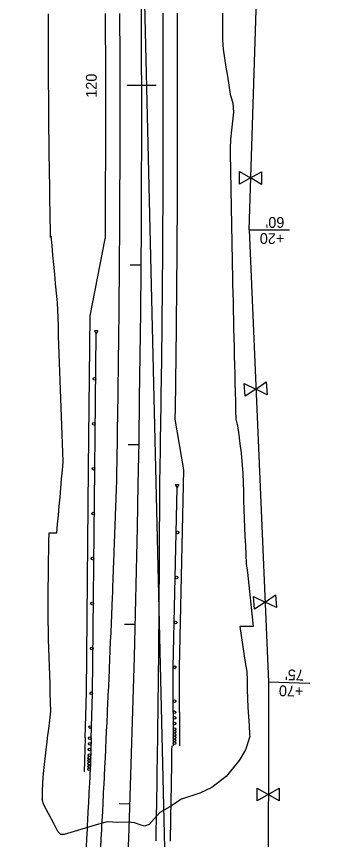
# Model space of a CAD drawing. Extents: x 634057 to 641016, y 287858 to 292331.
# Drawn here: x 634256.5 to 634429.5, y 290444.8 to 290902.9 of the extents above; entities that cross this region are included whole.
import ezdxf

# ---------------------------------------------------------------- set-up
doc = ezdxf.new("R2010")
doc.units = 0
for name, color, linetype in [('53', 7, 'Continuous'), ('R_50 Horz Alg PC PI PT', 7, 'Continuous'), ('R_50 Horz Alg Stations', 7, 'Continuous'), ('R_50 Horz Alg Ticks', 7, 'Continuous'), ('R_Draft', 7, 'Continuous'), ('R_Horz Alg', 7, 'Continuous'), ('R_No Plot', 7, 'Continuous'), ('R_Proposed Const Limits', 7, 'Continuous'), ('R_Proposed Road', 7, 'Continuous'), ('R_Proposed Shoulder', 7, 'Continuous'), ('R_ROW', 7, 'Continuous')]:
    doc.layers.add(name, color=color, linetype=linetype)

msp = doc.modelspace()

# ---------------------------------------------------------------- linework, layer by layer
at = {"layer": '53'}
for p, q in [((634385.92, 290784.2), (634408.37, 290784.07)), ((634396.7, 290532.52), (634419.69, 290531.88))]:
    msp.add_line(p, q, dxfattribs=at)
at = {"layer": 'R_50 Horz Alg PC PI PT'}
msp.add_lwpolyline([(634341.05, 290353.77), (634322.94, 291121.85)], dxfattribs=at)
at = {"layer": 'R_50 Horz Alg Ticks'}
for points in [[(634318.12, 290864.54), (634334.12, 290864.56)], [(634319.79, 290764.6), (634325.79, 290764.55)], [(634318.59, 290664.66), (634324.59, 290664.56)], [(634316.52, 290564.73), (634322.52, 290564.58)], [(634313.58, 290464.83), (634319.58, 290464.63)]]:
    msp.add_lwpolyline(points, dxfattribs=at)
at = {"layer": 'R_Draft'}
for p, q in [((634297.39, 290736.2), (634305.89, 290779.16)), ((634296.56, 290651.4), (634297.39, 290736.2)), ((634299.81, 290727.91), (634300.79, 290726.17)), ((634301.81, 290727.89), (634299.81, 290727.91)), ((634300.05, 290651.16), (634300.79, 290726.17)), ((634301.81, 290727.89), (634300.79, 290726.17)), ((634349.51, 290650.61), (634344.82, 290678.72)), ((634295.33, 290526.38), (634296.56, 290651.4)), ((634298.83, 290526.14), (634300.05, 290651.16)), ((634347.22, 290540.55), (634349.51, 290650.61)), ((634343.72, 290540.62), (634345.8, 290640.61)), ((634344.83, 290642.36), (634345.8, 290640.61)), ((634344.83, 290642.36), (634346.83, 290642.32)), ((634346.83, 290642.32), (634345.8, 290640.61)), ((634343.7, 290515.62), (634343.72, 290540.62)), ((634347.2, 290515.62), (634347.22, 290540.62)), ((634294.59, 290501.46), (634295.34, 290526.45)), ((634298.08, 290501.15), (634298.83, 290526.14)), ((634343.7, 290515.62), (634343.68, 290496.87)), ((634347.2, 290515.62), (634347.18, 290496.87)), ((634294.59, 290501.46), (634294.03, 290482.51)), ((634298.08, 290501.15), (634297.52, 290482.41))]:
    msp.add_line(p, q, dxfattribs=at)
for centre in [(634299.79, 290701.17), (634299.55, 290676.18), (634299.3, 290651.18), (634299.06, 290626.18), (634346.03, 290615.63), (634298.81, 290601.18), (634345.51, 290590.63), (634298.57, 290576.18), (634344.99, 290565.64), (634298.32, 290551.18), (634344.47, 290540.64), (634298.08, 290526.18), (634344.45, 290521.87), (634344.45, 290515.62), (634344.44, 290512.5), (634344.44, 290509.37), (634297.52, 290507.42), (634344.44, 290506.25), (634297.33, 290501.17), (634344.43, 290501.56), (634344.44, 290504.69), (634344.44, 290503.12), (634297.24, 290498.05), (634344.43, 290500), (634344.43, 290498.44), (634297.05, 290491.8), (634297.14, 290494.93), (634296.91, 290487.12), (634296.96, 290488.68), (634297, 290490.24), (634296.82, 290483.99), (634296.87, 290485.56)]:
    msp.add_circle(centre, 0.75, dxfattribs=at)
at = {"layer": 'R_Horz Alg'}
msp.add_arc((622866.97, 290851.82), 11459.16, 353.678846, 1.350269, dxfattribs=at)
at = {"layer": 'R_Proposed Const Limits'}
for points in [[(634270.89, 290467.15), (634271.01, 290471.25), (634271.06, 290476.55), (634271.5, 290481.52), (634272.08, 290486.48), (634272.65, 290491.45), (634273.23, 290496.41), (634273.54, 290499.06), (634273.81, 290501.38), (634274.38, 290506.35), (634274.96, 290511.31), (634275.5, 290516.28), (634275.4, 290521.28), (634275.29, 290526.28), (634275.19, 290531.28), (634275.02, 290536.28), (634274.84, 290541.28), (634274.67, 290546.29), (634274.51, 290551.29), (634274.34, 290556.29), (634274.19, 290561.3), (634274.05, 290566.29), (634274.05, 290566.3), (634274.02, 290570.59), (634274.05, 290575.58), (634274.1, 290580.57), (634274.16, 290585.55), (634274.22, 290590.54), (634274.29, 290595.53), (634274.36, 290600.52), (634274.45, 290605.5), (634274.54, 290610.49), (634274.62, 290615.47), (634278.85, 290615.41), (634279.34, 290620.39), (634279.81, 290625.37), (634280.26, 290630.35), (634280.72, 290635.34), (634281.16, 290640.32), (634281.58, 290645.3), (634282.02, 290650.28), (634282.4, 290655.26), (634282.4, 290655.27), (634282.22, 290660.25), (634282.02, 290665.24), (634281.83, 290670.24), (634281.64, 290675.23), (634281.45, 290680.22), (634281.26, 290685.21), (634281.06, 290690.2), (634280.87, 290695.19), (634280.69, 290700.18), (634280.5, 290705.17), (634280.32, 290710.16), (634280.14, 290715.15), (634280, 290720.15), (634279.87, 290725.14), (634279.75, 290730.13), (634279.63, 290735.12), (634279.19, 290743.67), (634278.7, 290748.95), (634278.2, 290754.24), (634277.71, 290759.53), (634277.23, 290764.82), (634276.74, 290770.11), (634276.26, 290775.39), (634275.8, 290780.68), (634275.44, 290779.87), (634275.33, 290784.85), (634275.26, 290789.83), (634275.17, 290794.81), (634275.09, 290799.78), (634275.01, 290804.76), (634274.94, 290809.74), (634274.87, 290814.72), (634274.8, 290819.7), (634274.73, 290824.67), (634274.66, 290829.65), (634274.6, 290834.63), (634274.55, 290839.61), (634274.5, 290844.59), (634274.45, 290849.56), (634274.41, 290854.54), (634274.37, 290859.52), (634274.35, 290864.49), (634274.33, 290869.47), (634274.32, 290874.45), (634274.3, 290879.43), (634274.29, 290884.4), (634274.28, 290889.38), (634274.26, 290894.36), (634274.25, 290899.34), (634274.24, 290904.31)], [(634371.03, 290904.76), (634371.05, 290899.74), (634371.06, 290894.72), (634371.08, 290889.7), (634371.37, 290884.68), (634372.17, 290879.66), (634372.97, 290874.65), (634373.77, 290869.63), (634374.58, 290864.61), (634375.39, 290859.59), (634376.84, 290854.56), (634377.2, 290849.54), (634376.66, 290844.52), (634376.13, 290839.5), (634375.6, 290834.48), (634375.31, 290829.46), (634375.38, 290824.44), (634375.46, 290819.41), (634375.55, 290814.39), (634375.65, 290809.37), (634375.73, 290804.35), (634375.82, 290799.33), (634375.92, 290794.3), (634376.03, 290789.28), (634376.14, 290784.26), (634376.25, 290779.24), (634376.26, 290778.82), (634376.35, 290774.21), (634376.44, 290769.19), (634376.53, 290764.17), (634376.63, 290759.14), (634376.73, 290754.12), (634376.83, 290749.1), (634376.94, 290744.07), (634377.05, 290739.05), (634377.16, 290734.03), (634377.28, 290729), (634377.42, 290723.98), (634377.56, 290718.95), (634377.64, 290713.93), (634377.73, 290708.9), (634377.88, 290703.88), (634378, 290698.85), (634378.1, 290693.83), (634378.23, 290688.8), (634378.39, 290683.78), (634378.49, 290678.75), (634379.46, 290675.13), (634380.12, 290670.06), (634380.77, 290664.99), (634381.46, 290659.93), (634381.46, 290659.92), (634382.37, 290648.58), (634382.51, 290643.57), (634382.67, 290638.55), (634382.85, 290633.54), (634383.01, 290628.53), (634383.19, 290623.51), (634383.4, 290618.5), (634383.57, 290613.48), (634383.57, 290613.47), (634383.78, 290608.46), (634384, 290603.45), (634384.21, 290598.43), (634384.91, 290593.41), (634388.17, 290563.28), (634380.63, 290563.4), (634381.4, 290558.38), (634382.17, 290553.36), (634382.93, 290548.33), (634383.73, 290543.31), (634384.54, 290538.28), (634384.81, 290533.27), (634384.89, 290528.25), (634384.98, 290523.24), (634385.15, 290518.22), (634385.56, 290513.2), (634385.86, 290508.19), (634386.15, 290503.17), (634386.21, 290502.19)], [(634386.21, 290502.19), (634383.91, 290494.64), (634380.34, 290488.84), (634373.15, 290479.83), (634365.05, 290473.84), (634358.46, 290470.57), (634348.24, 290467.19), (634341.77, 290463.07), (634336.27, 290459.82), (634333.07, 290456.38), (634330.35, 290453.23), (634327.75, 290452.26), (634325.33, 290452.99), (634322.19, 290454.02), (634318.68, 290454.5), (634312.88, 290454.26), (634306.89, 290454.62), (634302.06, 290453.41)], [(634302.06, 290453.41), (634282.99, 290447.53), (634281.16, 290447.63), (634279.41, 290449.26), (634277.29, 290453.68), (634271.65, 290464.14), (634270.82, 290467.15)]]:
    msp.add_lwpolyline(points, dxfattribs=at)
at = {"layer": 'R_Proposed Road'}
for points in [[(634303.38, 290440.19), (634303.65, 290445.18), (634303.91, 290450.17), (634304.03, 290452.58), (634304.16, 290455.15), (634304.42, 290460.14), (634304.67, 290465.13), (634304.92, 290470.12), (634305.12, 290474.14), (634305.17, 290475.11), (634305.42, 290480.09), (634305.66, 290485.08), (634305.9, 290490.07), (634306.14, 290495.06), (634306.18, 290495.7), (634306.38, 290500.05), (634306.62, 290505.04), (634306.85, 290510.03), (634307.08, 290515.02), (634307.19, 290517.26), (634307.31, 290520), (634307.54, 290524.99), (634307.76, 290529.98), (634307.99, 290534.97), (634308.16, 290538.83), (634308.21, 290539.96), (634308.43, 290544.95), (634308.64, 290549.94), (634308.86, 290554.93), (634309.07, 290559.92), (634309.09, 290560.39), (634309.28, 290564.91), (634309.48, 290569.91), (634309.69, 290574.9), (634309.89, 290579.89), (634309.98, 290581.96), (634310.09, 290584.88), (634310.29, 290589.87), (634310.49, 290594.86), (634310.68, 290599.85), (634310.82, 290603.54), (634310.87, 290604.84), (634311.06, 290609.83), (634311.25, 290614.83), (634311.44, 290619.82), (634311.62, 290624.81), (634311.63, 290625.11), (634311.8, 290629.8), (634311.98, 290634.79), (634312.16, 290639.79), (634312.25, 290644.78), (634312.28, 290646.69), (634312.34, 290649.77), (634312.43, 290654.77), (634312.51, 290659.76), (634312.59, 290664.76), (634312.65, 290668.27), (634312.67, 290669.75), (634312.75, 290674.75), (634312.83, 290679.74), (634312.9, 290684.73), (634312.98, 290689.73), (634312.98, 290689.86), (634313.04, 290694.72), (634313.11, 290699.72), (634313.18, 290704.71), (634313.24, 290709.7), (634313.26, 290711.44), (634313.3, 290714.7), (634313.36, 290719.69), (634313.42, 290724.69), (634313.47, 290729.68), (634313.51, 290733.03), (634313.52, 290734.68), (634313.57, 290739.67), (634313.62, 290744.67), (634313.67, 290749.66), (634313.71, 290754.61), (634313.71, 290754.66), (634313.75, 290759.65), (634313.79, 290764.64), (634313.83, 290769.64), (634313.86, 290774.63), (634313.87, 290776.2), (634313.9, 290779.63), (634313.93, 290784.62), (634313.95, 290789.62), (634313.98, 290794.61), (634314, 290797.79), (634314, 290799.61), (634314.03, 290804.6), (634314.05, 290809.6), (634314.06, 290814.59), (634314.08, 290819.37), (634314.08, 290819.59), (634314.09, 290824.58), (634314.1, 290829.58), (634314.11, 290834.57), (634314.12, 290839.57), (634314.12, 290840.96), (634314.12, 290844.56), (634314.12, 290849.55), (634314.12, 290854.55), (634314.12, 290859.54), (634314.12, 290862.55), (634314.12, 290864.54), (634314.11, 290869.53), (634314.1, 290874.53), (634314.09, 290879.52), (634314.08, 290884.13), (634314.08, 290884.52), (634314.06, 290889.51), (634314.04, 290894.51), (634314.02, 290899.5), (634314, 290904.5)], [(634334.13, 290444.1), (634334.22, 290449.1), (634334.26, 290451.53), (634334.31, 290454.11), (634334.4, 290459.12), (634334.49, 290464.12), (634334.57, 290469.13), (634334.64, 290473.17), (634334.66, 290474.13), (634334.74, 290479.14), (634334.81, 290484.15), (634334.89, 290489.15), (634334.96, 290494.16), (634334.97, 290494.8), (634335.04, 290499.17), (634335.1, 290504.17), (634335.17, 290509.18), (634335.24, 290514.19), (634335.27, 290516.44), (634335.3, 290519.19), (634335.36, 290524.2), (634335.42, 290529.21), (634335.48, 290534.21), (634335.52, 290538.08), (634335.53, 290539.22), (634335.58, 290544.22), (634335.63, 290549.23), (634335.68, 290554.24), (634335.72, 290559.24), (634335.73, 290559.72), (634335.77, 290564.25), (634335.81, 290569.26), (634335.85, 290574.26), (634335.88, 290579.27), (634335.9, 290581.35), (634335.92, 290584.28), (634335.95, 290589.28), (634335.98, 290594.29), (634336.01, 290599.29), (634336.03, 290602.99), (634336.04, 290604.3), (634336.06, 290609.31), (634336.08, 290614.31), (634336.1, 290619.32), (634336.12, 290624.32), (634336.12, 290624.62), (634336.13, 290629.33), (634336.14, 290634.34), (634336.15, 290639.34), (634336.25, 290644.35), (634336.28, 290646.26), (634336.34, 290649.35), (634336.42, 290654.36), (634336.51, 290659.36), (634336.59, 290664.36), (634336.65, 290667.89), (634336.67, 290669.37), (634336.75, 290674.37), (634336.83, 290679.38), (634336.9, 290684.38), (634336.97, 290689.39), (634336.97, 290689.52), (634337.04, 290694.39), (634337.11, 290699.4), (634337.18, 290704.4), (634337.24, 290709.41), (634337.26, 290711.15), (634337.3, 290714.41), (634337.36, 290719.42), (634337.42, 290724.42), (634337.47, 290729.43), (634337.51, 290732.78), (634337.52, 290734.43), (634337.57, 290739.44), (634337.62, 290744.44), (634337.67, 290749.45), (634337.71, 290754.41), (634337.71, 290754.45), (634337.75, 290759.46), (634337.79, 290764.46), (634337.83, 290769.47), (634337.86, 290774.47), (634337.87, 290776.04), (634337.89, 290779.48), (634337.93, 290784.48), (634337.95, 290789.49), (634337.98, 290794.49), (634338, 290797.67), (634338, 290799.5), (634338.03, 290804.5), (634338.04, 290809.51), (634338.06, 290814.51), (634338.08, 290819.3), (634338.08, 290819.52), (634338.09, 290824.52), (634338.1, 290829.53), (634338.11, 290834.53), (634338.12, 290839.54), (634338.12, 290840.94), (634338.12, 290844.54), (634338.12, 290849.55), (634338.12, 290854.56), (634338.12, 290859.56), (634338.12, 290862.57), (634338.12, 290864.57), (634338.11, 290869.57), (634338.1, 290874.58), (634338.09, 290879.58), (634338.08, 290884.2), (634338.08, 290884.59), (634338.06, 290889.59), (634338.04, 290894.6), (634338.02, 290899.6), (634338, 290904.61)]]:
    msp.add_lwpolyline(points, dxfattribs=at)
at = {"layer": 'R_Proposed Shoulder'}
for points in [[(634305.89, 290779.16), (634305.9, 290779.68), (634305.93, 290784.67), (634305.95, 290789.66), (634305.98, 290794.65), (634306, 290797.82), (634306, 290799.64), (634306.03, 290804.63), (634306.05, 290809.63), (634306.06, 290814.62), (634306.08, 290819.4), (634306.08, 290819.61), (634306.09, 290824.6), (634306.1, 290829.59), (634306.11, 290834.58), (634306.12, 290839.57), (634306.12, 290840.97), (634306.12, 290844.57), (634306.12, 290849.56), (634306.12, 290854.55), (634306.12, 290859.54), (634306.12, 290862.54), (634306.12, 290864.53), (634306.11, 290869.52), (634306.1, 290874.51), (634306.09, 290879.5), (634306.08, 290884.11), (634306.08, 290884.5), (634306.06, 290889.49), (634306.04, 290894.48), (634306.02, 290899.47), (634306, 290904.46)], [(634344.82, 290678.72), (634344.83, 290679.26), (634344.9, 290684.27), (634344.97, 290689.27), (634344.97, 290689.4), (634345.04, 290694.28), (634345.11, 290699.29), (634345.17, 290704.3), (634345.24, 290709.31), (634345.26, 290711.05), (634345.3, 290714.32), (634345.36, 290719.32), (634345.41, 290724.33), (634345.47, 290729.34), (634345.5, 290732.69), (634345.52, 290734.35), (634345.57, 290739.36), (634345.62, 290744.37), (634345.67, 290749.38), (634345.71, 290754.34), (634345.71, 290754.38), (634345.75, 290759.39), (634345.79, 290764.4), (634345.83, 290769.41), (634345.86, 290774.42), (634345.87, 290775.99), (634345.89, 290779.43), (634345.93, 290784.44), (634345.95, 290789.44), (634345.98, 290794.45), (634346, 290797.63), (634346, 290799.46), (634346.03, 290804.47), (634346.04, 290809.48), (634346.06, 290814.49), (634346.08, 290819.28), (634346.08, 290819.5), (634346.09, 290824.5), (634346.1, 290829.51), (634346.11, 290834.52), (634346.12, 290839.53), (634346.12, 290840.93), (634346.12, 290844.54), (634346.12, 290849.55), (634346.12, 290854.56), (634346.12, 290859.57), (634346.12, 290862.58), (634346.12, 290864.57), (634346.11, 290869.58), (634346.1, 290874.59), (634346.09, 290879.6), (634346.08, 290884.22), (634346.08, 290884.61), (634346.06, 290889.62), (634346.04, 290894.63), (634346.02, 290899.64), (634346, 290904.64)], [(634342.12, 290443.81), (634342.22, 290448.82), (634342.26, 290451.25), (634342.31, 290453.83), (634342.4, 290458.84), (634342.48, 290463.85), (634342.57, 290468.86), (634342.63, 290472.9), (634342.65, 290473.87), (634342.73, 290478.88), (634342.81, 290483.89), (634342.89, 290488.9), (634342.96, 290493.91), (634342.97, 290494.55), (634343, 290496.88)], [(634295.39, 290440.48), (634295.65, 290445.46), (634295.91, 290450.45), (634296.04, 290452.86), (634296.17, 290455.43), (634296.42, 290460.42), (634296.68, 290465.4), (634296.93, 290470.38), (634297.13, 290474.4), (634297.18, 290475.37), (634297.42, 290480.35), (634297.52, 290482.41)]]:
    msp.add_lwpolyline(points, dxfattribs=at)
at = {"layer": 'R_ROW'}
for p, q in [((634380.51, 290809.5), (634380.57, 290816.57)), ((634386.67, 290812.98), (634380.51, 290809.5)), ((634380.57, 290816.57), (634386.67, 290812.98)), ((634386.67, 290812.98), (634392.82, 290816.47)), ((634392.76, 290809.4), (634386.67, 290812.98)), ((634392.82, 290816.47), (634392.76, 290809.4)), ((634383.22, 290698.56), (634389.58, 290695.47)), ((634383.73, 290691.5), (634383.22, 290698.56)), ((634389.58, 290695.47), (634395.43, 290699.44)), ((634395.43, 290699.44), (634395.94, 290692.38)), ((634389.58, 290695.47), (634383.73, 290691.5)), ((634395.94, 290692.38), (634389.58, 290695.47)), ((634388.4, 290580.07), (634394.76, 290576.98)), ((634388.9, 290573.01), (634388.4, 290580.07)), ((634394.76, 290576.98), (634400.61, 290580.94)), ((634400.61, 290580.94), (634401.12, 290573.89)), ((634394.76, 290576.98), (634388.9, 290573.01)), ((634401.12, 290573.89), (634394.76, 290576.98)), ((634390.42, 290466.32), (634390.43, 290473.4)), ((634396.55, 290469.85), (634390.42, 290466.32)), ((634390.43, 290473.4), (634396.55, 290469.85)), ((634396.55, 290469.85), (634402.67, 290473.39)), ((634402.67, 290466.31), (634396.55, 290469.85)), ((634402.67, 290473.39), (634402.67, 290466.31))]:
    msp.add_line(p, q, dxfattribs=at)
for points in [[(634385.92, 290784.2), (634404.17, 291355.03)], [(634385.92, 290784.2), (634396.7, 290532.52), (634396.26, 290266.17), (634429.51, 290195.43)]]:
    msp.add_lwpolyline(points, dxfattribs=at)

# ---------------------------------------------------------------- texts
at = {"layer": '53'}
for s, rotation, p in [("60'  ", 179.6637, (634405.5, 290791.21)), ('+20 ', 179.6637, (634405.45, 290782.21)), ("75'  ", 178.4137, (634416.4, 290539.26)), ('+70 ', 178.4137, (634416.15, 290530.26))]:
    msp.add_text(s, height=6, rotation=rotation, dxfattribs=at).set_placement(p)
at = {"layer": 'R_50 Horz Alg Stations'}
msp.add_text('120', height=6, rotation=90.0637, dxfattribs=at).set_placement((634301.12, 290857.65))
at = {"layer": 'R_No Plot'}
msp.add_text('+', height=0.1, rotation=87.1576, dxfattribs=at).set_placement((634312.47, 290654.72))
msp.add_text('+', height=0.1, rotation=87.1576, dxfattribs=at).set_placement((634312.47, 290654.72))
msp.add_text('+', height=0.1, rotation=87.1576, dxfattribs=at).set_placement((634312.47, 290654.72))

doc.saveas('drawing.dxf')
